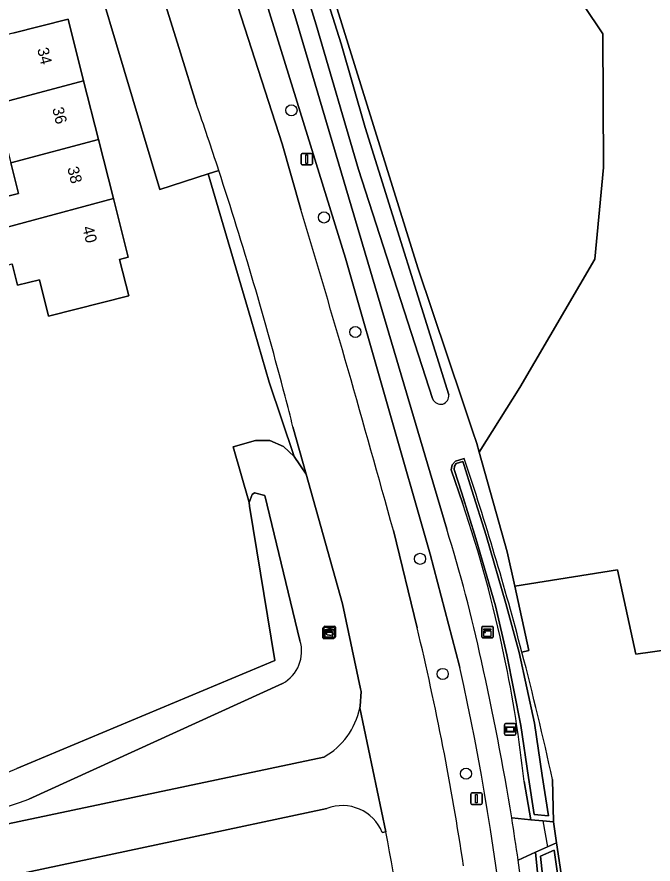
# Model space of a CAD drawing. Extents: x 162510 to 163918, y 388494 to 389774.
# Drawn here: x 162618.4 to 162674.3, y 389627.2 to 389701.6 of the extents above; entities that cross this region are included whole.
import ezdxf

# ---------------------------------------------------------------- set-up
doc = ezdxf.new("R2010")
doc.units = 0
for name, color, linetype in [('IMGEO_Berm_groen', 7, 'Continuous'), ('IMGEO_Boom', 7, 'Continuous'), ('IMGEO_Duiker', 7, 'Continuous'), ('IMGEO_Erf', 7, 'Continuous'), ('IMGEO_Fietspad_gesloten', 7, 'Continuous'), ('IMGEO_Grasland_agrarisch', 7, 'Continuous'), ('IMGEO_Groenvoorziening', 7, 'Continuous'), ('IMGEO_Kast', 7, 'Continuous'), ('IMGEO_Lichtmast', 7, 'Continuous'), ('IMGEO_Oever', 7, 'Continuous'), ('IMGEO_Pand', 7, 'Continuous'), ('IMGEO_Pand_nummerreeks', 7, 'Continuous'), ('IMGEO_Rijbaan_lokaal_gesloten', 7, 'Continuous'), ('IMGEO_Rijbaan_lokaal_halfverhard', 7, 'Continuous'), ('IMGEO_Rijbaan_lokaal_open', 7, 'Continuous'), ('IMGEO_Rioolput', 7, 'Continuous'), ('IMGEO_Verklikker', 7, 'Continuous'), ('IMGEO_Voetpad_halfverhard', 7, 'Continuous'), ('IMGEO_Waterloop', 7, 'Continuous')]:
    doc.layers.add(name, color=color, linetype=linetype)

msp = doc.modelspace()

# ---------------------------------------------------------------- linework, layer by layer
at = {"layer": 'IMGEO_Berm_groen'}
for points in [[(162657.306, 389644.486), (162657.276, 389644.598), (162654.694, 389654.432), (162647.267, 389680.414), (162625.711, 389750), (162623.648, 389756.662), (162621.623, 389756.628), (162621.069, 389756.619)], [(162621.069, 389756.619), (162623.811, 389747.513), (162627.663, 389734.752), (162631.516, 389722.082), (162634.181, 389714.087), (162636.629, 389706.24), (162641.701, 389690.442), (162643.356, 389684.664)], [(162651.468, 389656.503), (162653.554, 389647.978)], [(162645.63, 389632.117), (162606.04, 389623.696)], [(162650.812, 389630.07), (162650.498, 389630.008)]]:
    msp.add_lwpolyline(points, dxfattribs=at)
for centre, radius, start, end in [((161544.624, 389352.917), 1147.723, 15.337949, 16.800985), ((162411.673, 389589.955), 248.743, 8.58477, 13.48924), ((162441.799, 389596.346), 220.818, 359.26131, 12.59207), ((162647.001, 389628.609), 3.767, 21.80971, 111.34215), ((162495.406, 389600.134), 158.263, 0.58051, 10.90354)]:
    msp.add_arc(centre, radius, start, end, dxfattribs=at)
at = {"layer": 'IMGEO_Boom'}
for centre in [(162642.53, 389693.381), (162645.384, 389683.977), (162648.134, 389673.926), (162653.814, 389654.027), (162655.802, 389643.929), (162657.847, 389635.178)]:
    msp.add_circle(centre, 0.489, dxfattribs=at)
at = {"layer": 'IMGEO_Duiker'}
msp.add_lwpolyline([(162664.576, 389631.03), (162664.992, 389628.753)], dxfattribs=at)
at = {"layer": 'IMGEO_Erf'}
for points in [[(162618.447, 389635.627), (162641.074, 389645.121), (162638.861, 389658.639), (162638.809, 389658.955), (162637.413, 389663.853), (162639.383, 389664.401), (162640.622, 389664.401), (162641.833, 389663.89), (162642.776, 389663.003), (162640.565, 389669.518), (162638.969, 389675.09), (162635.223, 389687.803), (162630.982, 389686.434), (162627.859, 389696.902), (162625.249, 389705.649)], [(162618.089, 389700.135), (162622.936, 389701.361), (162624.3, 389695.971), (162625.603, 389690.821), (162626.911, 389685.654), (162628.217, 389680.492), (162627.441, 389680.296), (162628.251, 389677.097), (162621.222, 389675.319), (162620.413, 389678.518), (162618.51, 389678.037), (162618.038, 389679.908)], [(162613.217, 389684.726), (162618.587, 389686.084), (162617.91, 389688.761)], [(162683.399, 389647.166), (162672.749, 389645.659), (162671.119, 389653.063), (162662.113, 389651.634), (162663.364, 389645.997), (162662.745, 389645.853)], [(162665.428, 389634.667), (162665.504, 389630.941), (162665.782, 389629.105), (162667.72, 389616.266), (162671.531, 389596.525), (162682.772, 389600.017), (162694.884, 389604.331), (162700.737, 389606.566), (162706.577, 389609.521), (162708.451, 389610.469), (162716.702, 389614.898), (162716.891, 389614.546), (162708.636, 389610.114), (162706.758, 389609.164), (162700.899, 389606.2), (162695.022, 389603.956), (162682.898, 389599.637), (162671.607, 389596.13), (162671.64, 389595.959), (162671.78, 389595.085)]]:
    msp.add_lwpolyline(points, dxfattribs=at)
for centre, radius, start, end in [((162400.973, 389577.151), 270.637, 12.27004, 14.70554), ((162593.871, 389692.296), 61.768, 281.18586, 293.44497)]:
    msp.add_arc(centre, radius, start, end, dxfattribs=at)
at = {"layer": 'IMGEO_Fietspad_gesloten'}
for points in [[(162656.158, 389656.625), (162642.905, 389701.409), (162627.834, 389750), (162625.756, 389756.697), (162623.648, 389756.662)], [(162623.648, 389756.662), (162625.711, 389750), (162647.267, 389680.414), (162654.694, 389654.432), (162657.276, 389644.598), (162657.306, 389644.486)]]:
    msp.add_lwpolyline(points, dxfattribs=at)
for centre, radius, start, end in [((162533.694, 389618.315), 128.317, 12.03732, 17.37116), ((162444.215, 389596.393), 220.417, 9.11335, 12.75985), ((162441.799, 389596.346), 220.818, 359.26131, 12.59207), ((162449.24, 389597.126), 215.34, 8.13643, 9.13247), ((162443.365, 389596.276), 221.276, 0.5906, 8.13893)]:
    msp.add_arc(centre, radius, start, end, dxfattribs=at)
at = {"layer": 'IMGEO_Grasland_agrarisch'}
msp.add_lwpolyline([(162687.277, 389757.733), (162652.361, 389744.846), (162649.788, 389743.642), (162655.173, 389728.688), (162659.589, 389717.108), (162663.344, 389709.783), (162669.846, 389700.093), (162669.917, 389688.356), (162669.136, 389680.314), (162662.579, 389669.049), (162659.003, 389663.387), (162661.443, 389654.652), (162662.113, 389651.634), (162671.119, 389653.063), (162672.749, 389645.659), (162683.399, 389647.166)], dxfattribs=at)
at = {"layer": 'IMGEO_Groenvoorziening'}
for points in [[(162654.908, 389668.091), (162648.424, 389688.196), (162644.71, 389700.887), (162633.95, 389735.77), (162629.441, 389750), (162627.311, 389756.724), (162625.756, 389756.697), (162627.834, 389750), (162642.905, 389701.409), (162656.158, 389656.625)], [(162629.565, 389756.763), (162628.661, 389756.746), (162630.798, 389750), (162646.883, 389699.203), (162649.01, 389691.856), (162656.336, 389668.425)], [(162662.745, 389645.853), (162663.364, 389645.997), (162662.113, 389651.634), (162661.443, 389654.652), (162659.003, 389663.387), (162658.792, 389664.143), (162658.415, 389665.263), (162657.534, 389667.881), (162653.602, 389679.561), (162629.565, 389756.763)], [(162648.52, 389640.952), (162648.546, 389641.092), (162648.639, 389642.388), (162648.587, 389642.631), (162646.993, 389650.091), (162643.825, 389661.448), (162642.776, 389663.003), (162641.833, 389663.89), (162640.622, 389664.401), (162639.383, 389664.401), (162637.413, 389663.853), (162638.809, 389658.955), (162639.082, 389659.667), (162639.277, 389659.825), (162640.198, 389659.584), (162643.278, 389646.86)], [(162657.557, 389658.857), (162656.55, 389661.826), (162656.621, 389662.265), (162656.908, 389662.604), (162657.688, 389662.823)], [(162641.751, 389643.1), (162619.481, 389632.945)], [(162606.309, 389629.62), (162606.57, 389628.425), (162645.367, 389636.64)], [(162661.85, 389631.304), (162663.534, 389631.13), (162662.936, 389634.499)], [(162664.781, 389619.716), (162663.942, 389628.285), (162662.412, 389627.603)]]:
    msp.add_lwpolyline(points, dxfattribs=at)
msp.add_lwpolyline([(162629.565, 389756.763), (162653.602, 389679.561), (162657.534, 389667.881), (162658.415, 389665.263), (162658.792, 389664.143), (162659.003, 389663.387), (162662.579, 389669.049), (162669.136, 389680.314), (162669.917, 389688.356), (162669.846, 389700.093), (162663.344, 389709.783), (162659.589, 389717.108), (162655.173, 389728.688), (162649.788, 389743.642), (162647.635, 389742.802), (162643.424, 389750), (162639.379, 389756.914), (162639.372, 389756.927), (162636.47, 389756.878), (162631.645, 389756.797)], close=True, dxfattribs=at)
for centre, radius, start, end in [((162655.556, 389668.344), 0.784, 289.18667, 5.91611), ((162655.643, 389668.371), 0.786, 200.89435, 282.58714), ((162402.456, 389577.526), 269.107, 14.70848, 18.47926), ((162549.33, 389622.204), 114.265, 11.76157, 18.70948), ((162533.694, 389618.315), 128.317, 12.03732, 17.37116), ((162640.223, 389645.911), 3.199, 298.53368, 17.26051), ((162444.215, 389596.393), 220.417, 9.11335, 12.75985), ((162549.36, 389622.165), 114.244, 6.19805, 11.78412), ((162642.302, 389642.19), 6.34, 298.91007, 348.74025), ((162597.624, 389691.778), 62.762, 277.95404, 290.38031), ((162443.365, 389596.276), 221.276, 0.5906, 8.13893)]:
    msp.add_arc(centre, radius, start, end, dxfattribs=at)
at = {"layer": 'IMGEO_Kast'}
for p, q in [((162659.299, 389648.1), (162660.14, 389648.1)), ((162660.14, 389648.1), (162659.299, 389648.1)), ((162645.296, 389647.107), (162645.296, 389647.948)), ((162645.296, 389647.948), (162645.296, 389647.107)), ((162645.371, 389648.032), (162646.212, 389648.032)), ((162646.212, 389648.032), (162645.371, 389648.032)), ((162646.296, 389647.957), (162646.296, 389647.116)), ((162646.296, 389647.116), (162646.296, 389647.957)), ((162659.224, 389647.175), (162659.224, 389648.016)), ((162659.224, 389648.016), (162659.224, 389647.175)), ((162660.224, 389648.025), (162660.224, 389647.184)), ((162660.224, 389647.184), (162660.224, 389648.025)), ((162646.221, 389647.032), (162645.38, 389647.032)), ((162645.38, 389647.032), (162646.221, 389647.032)), ((162660.149, 389647.1), (162659.308, 389647.1)), ((162659.308, 389647.1), (162660.149, 389647.1))]:
    msp.add_line(p, q, dxfattribs=at)
for points in [[(162645.491, 389647.822), (162646.091, 389647.822), (162646.091, 389647.737), (162645.491, 389647.737), (162645.491, 389647.822)], [(162645.491, 389647.647), (162646.091, 389647.647), (162646.091, 389647.158), (162645.491, 389647.158), (162645.491, 389647.647)], [(162659.419, 389647.89), (162660.019, 389647.89), (162660.019, 389647.805), (162659.419, 389647.805), (162659.419, 389647.89)], [(162659.419, 389647.715), (162660.019, 389647.715), (162660.019, 389647.226), (162659.419, 389647.226), (162659.419, 389647.715)]]:
    msp.add_lwpolyline(points, dxfattribs=at)
for centre in [(162645.575, 389647.496), (162659.503, 389647.564)]:
    msp.add_circle(centre, 0.0377, dxfattribs=at)
for centre, start, end in [((162659.302, 389648.022), 92.4484, 184.28452), ((162659.302, 389648.022), 92.4484, 184.28452), ((162660.146, 389648.022), 2.4484, 94.28452), ((162660.146, 389648.022), 2.4484, 94.28452), ((162645.374, 389647.954), 92.4484, 184.28452), ((162645.374, 389647.954), 92.4484, 184.28452), ((162646.218, 389647.954), 2.4484, 94.28452), ((162646.218, 389647.954), 2.4484, 94.28452), ((162645.374, 389647.11), 182.4484, 274.28452), ((162645.374, 389647.11), 182.4484, 274.28452), ((162646.218, 389647.11), 272.4484, 4.28452), ((162646.218, 389647.11), 272.4484, 4.28452), ((162659.302, 389647.178), 182.4484, 274.28452), ((162659.302, 389647.178), 182.4484, 274.28452), ((162660.146, 389647.178), 272.4484, 4.28452), ((162660.146, 389647.178), 272.4484, 4.28452)]:
    msp.add_arc(centre, 0.0779, start, end, dxfattribs=at)
at = {"layer": 'IMGEO_Lichtmast'}
for p, q in [((162643.371, 389688.691), (162643.371, 389689.491)), ((162643.371, 389689.491), (162643.371, 389688.691)), ((162643.471, 389689.591), (162644.261, 389689.591)), ((162644.261, 389689.591), (162643.471, 389689.591)), ((162644.361, 389689.491), (162644.361, 389688.691)), ((162644.361, 389688.691), (162644.361, 389689.491)), ((162644.261, 389688.591), (162643.471, 389688.591)), ((162643.471, 389688.591), (162644.261, 389688.591)), ((162658.266, 389632.587), (162658.266, 389633.387)), ((162658.266, 389633.387), (162658.266, 389632.587)), ((162658.366, 389633.487), (162659.156, 389633.487)), ((162659.156, 389633.487), (162658.366, 389633.487)), ((162659.256, 389633.387), (162659.256, 389632.587)), ((162659.256, 389632.587), (162659.256, 389633.387)), ((162659.156, 389632.487), (162658.366, 389632.487)), ((162658.366, 389632.487), (162659.156, 389632.487))]:
    msp.add_line(p, q, dxfattribs=at)
for points in [[(162643.791, 389689.466), (162643.941, 389689.466), (162643.941, 389688.716), (162643.791, 389688.716), (162643.791, 389689.466)], [(162658.686, 389633.362), (162658.836, 389633.362), (162658.836, 389632.612), (162658.686, 389632.612), (162658.686, 389633.362)]]:
    msp.add_lwpolyline(points, dxfattribs=at)
for centre, start, end in [((162643.471, 389689.491), 90, 180), ((162643.471, 389689.491), 90, 180), ((162644.261, 389689.491), 0, 90), ((162644.261, 389689.491), 360, 90), ((162643.471, 389688.691), 180, 270), ((162643.471, 389688.691), 180, 270), ((162644.261, 389688.691), 270, 0), ((162644.261, 389688.691), 270, 0), ((162658.366, 389633.387), 90, 180), ((162658.366, 389633.387), 90, 180), ((162659.156, 389633.387), 0, 90), ((162659.156, 389633.387), 360, 90), ((162658.366, 389632.587), 180, 270), ((162658.366, 389632.587), 180, 270), ((162659.156, 389632.587), 270, 0), ((162659.156, 389632.587), 270, 0)]:
    msp.add_arc(centre, 0.1, start, end, dxfattribs=at)
at = {"layer": 'IMGEO_Oever'}
for points in [[(162657.688, 389662.823), (162656.908, 389662.604), (162656.621, 389662.265), (162656.55, 389661.826), (162657.557, 389658.857)], [(162662.936, 389634.499), (162663.534, 389631.13), (162664.576, 389631.03), (162665.504, 389630.941), (162665.428, 389634.667)]]:
    msp.add_lwpolyline(points, dxfattribs=at)
for points in [[(162665.077, 389631.473), (162663.826, 389631.604), (162663.317, 389634.841), (162662.644, 389639.412), (162661.418, 389645.593), (162660.421, 389649.903), (162658.716, 389655.825), (162657.478, 389659.779), (162656.79, 389661.874), (162656.82, 389662.147), (162656.983, 389662.391), (162657.578, 389662.566), (162657.69, 389662.206), (162658.359, 389660.059), (162659.598, 389656.087), (162661.342, 389650.121), (162662.508, 389645.819), (162663.843, 389639.619), (162664.52, 389635.025)], [(162665.782, 389629.105), (162664.992, 389628.753), (162663.942, 389628.285), (162664.781, 389619.716), (162669.021, 389596.399), (162670.086, 389595.68), (162671.64, 389595.959), (162671.607, 389596.13), (162671.531, 389596.525), (162667.72, 389616.266)], [(162665.576, 389628.466), (162666.774, 389620.114), (162667.664, 389614.753), (162668.816, 389608.963), (162671.265, 389596.221), (162670.102, 389596.028), (162669.408, 389596.502), (162667.305, 389608.699), (162666.28, 389614.493), (162665.235, 389619.894), (162664.385, 389627.945)]]:
    msp.add_lwpolyline(points, close=True, dxfattribs=at)
for centre, radius, start, end in [((162402.456, 389577.526), 269.107, 14.70848, 18.47926), ((162549.33, 389622.204), 114.265, 11.76157, 18.70948), ((162400.973, 389577.151), 270.637, 12.27004, 14.70554), ((162549.36, 389622.165), 114.244, 6.19805, 11.78412)]:
    msp.add_arc(centre, radius, start, end, dxfattribs=at)
at = {"layer": 'IMGEO_Pand'}
for points in [[(162622.936, 389701.361), (162618.089, 389700.135), (162615.181, 389699.399), (162615.887, 389696.671), (162610.605, 389695.335), (162611.188, 389693.03), (162611.317, 389692.522), (162624.3, 389695.971)], [(162617.91, 389688.761), (162625.603, 389690.821), (162624.3, 389695.971), (162611.317, 389692.522), (162611.997, 389689.835), (162617.299, 389691.177)], [(162612.029, 389681.374), (162613.873, 389682.136), (162626.911, 389685.654), (162625.603, 389690.821), (162617.91, 389688.761), (162618.587, 389686.084), (162613.217, 389684.726), (162611.304, 389684.242)], [(162626.911, 389685.654), (162613.873, 389682.136), (162612.029, 389681.374), (162612.267, 389680.432), (162611.785, 389680.309), (162611.202, 389680.161), (162610.332, 389679.939), (162610.133, 389679.889), (162611.263, 389675.42), (162615.49, 389676.489), (162614.83, 389679.097), (162617.516, 389679.776), (162618.038, 389679.908), (162618.51, 389678.037), (162620.413, 389678.518), (162621.222, 389675.319), (162628.251, 389677.097), (162627.441, 389680.296), (162628.217, 389680.492)]]:
    msp.add_lwpolyline(points, close=True, dxfattribs=at)
at = {"layer": 'IMGEO_Rijbaan_lokaal_gesloten'}
for points in [[(162643.356, 389684.664), (162641.701, 389690.442), (162636.629, 389706.24), (162634.181, 389714.087), (162631.516, 389722.082), (162627.663, 389734.752), (162623.811, 389747.513), (162621.069, 389756.619), (162614.746, 389756.512)], [(162614.746, 389756.512), (162616.763, 389750), (162624.646, 389724.639), (162625.196, 389722.87), (162627.614, 389715.092), (162627.673, 389714.901), (162630.082, 389707.151), (162632.791, 389698.435), (162634.173, 389693.988)], [(162642.662, 389665.619), (162643.825, 389661.448), (162646.993, 389650.091), (162648.587, 389642.631), (162648.639, 389642.388), (162648.546, 389641.092), (162648.52, 389640.952), (162650.812, 389630.07)], [(162653.554, 389647.978), (162651.468, 389656.503)]]:
    msp.add_lwpolyline(points, dxfattribs=at)
for centre, radius, start, end in [((162310.638, 389581.786), 342.438, 18.08773, 19.12653), ((162307.447, 389580.769), 345.788, 14.66153, 18.08373), ((161544.624, 389352.917), 1147.723, 15.337949, 16.800985), ((162297.232, 389578.23), 356.312, 14.19723, 14.64087), ((162411.673, 389589.955), 248.743, 8.58477, 13.48924), ((162495.406, 389600.134), 158.263, 0.58051, 10.90354)]:
    msp.add_arc(centre, radius, start, end, dxfattribs=at)
at = {"layer": 'IMGEO_Rijbaan_lokaal_halfverhard'}
msp.add_lwpolyline([(162636.154, 389688.104), (162635.223, 389687.803), (162638.969, 389675.09), (162640.565, 389669.518), (162642.776, 389663.003), (162643.825, 389661.448), (162642.662, 389665.619)], dxfattribs=at)
for centre, radius, start, end in [((162307.447, 389580.769), 345.788, 14.66153, 18.08373), ((162297.232, 389578.23), 356.312, 14.19723, 14.64087)]:
    msp.add_arc(centre, radius, start, end, dxfattribs=at)
at = {"layer": 'IMGEO_Rijbaan_lokaal_open'}
for points in [[(162632.791, 389698.435), (162630.082, 389707.151), (162628.847, 389706.767), (162625.249, 389705.649), (162627.859, 389696.902), (162630.982, 389686.434), (162635.223, 389687.803), (162636.154, 389688.104)], [(162634.173, 389693.988), (162632.791, 389698.435)], [(162650.498, 389630.008), (162650.812, 389630.07), (162648.52, 389640.952)], [(162645.367, 389636.64), (162606.57, 389628.425), (162605.4, 389628.177)], [(162606.04, 389623.696), (162645.63, 389632.117)]]:
    msp.add_lwpolyline(points, dxfattribs=at)
for centre, radius, start, end in [((162310.638, 389581.786), 342.438, 18.08773, 19.12653), ((162642.302, 389642.19), 6.34, 298.91007, 348.74025), ((162647.001, 389628.609), 3.767, 21.80971, 111.34215)]:
    msp.add_arc(centre, radius, start, end, dxfattribs=at)
at = {"layer": 'IMGEO_Rioolput'}
for p, q in [((162645.461, 389648.115), (162646.313, 389648.115)), ((162645.386, 389647.189), (162645.386, 389648.041)), ((162645.645, 389647.609), (162645.645, 389647.621)), ((162646.083, 389647.572), (162645.685, 389647.572)), ((162645.688, 389647.658), (162646.086, 389647.658)), ((162645.897, 389647.335), (162645.872, 389647.335)), ((162645.874, 389647.895), (162645.899, 389647.895)), ((162646.129, 389647.621), (162646.129, 389647.609)), ((162646.387, 389648.041), (162646.387, 389647.189)), ((162646.313, 389647.115), (162645.461, 389647.115))]:
    msp.add_line(p, q, dxfattribs=at)
for points in [[(162645.461, 389648.115), (162646.313, 389648.115)], [(162645.386, 389647.189), (162645.386, 389648.041)], [(162646.387, 389648.041), (162646.387, 389647.189)], [(162646.313, 389647.115), (162645.461, 389647.115)]]:
    msp.add_lwpolyline(points, dxfattribs=at)
for centre, radius, start, end in [((162645.463, 389648.039), 0.0765, 91.55205, 178.44795), ((162645.463, 389648.039), 0.0765, 91.55205, 178.44795), ((162646.311, 389648.039), 0.0765, 1.55205, 88.44795), ((162646.311, 389648.039), 0.0765, 1.55205, 88.44795), ((162645.685, 389647.618), 0.0403, 85.87752, 175.75265), ((162645.682, 389647.608), 0.0366, 178.93798, 274.71019), ((162646.086, 389647.615), 0.043, 264.86636, 352.45326), ((162646.09, 389647.62), 0.0386, 1.73085, 96.63898), ((162645.463, 389647.191), 0.0765, 181.55205, 268.44795), ((162645.463, 389647.191), 0.0765, 181.55205, 268.44795), ((162646.311, 389647.191), 0.0765, 271.55205, 358.44795), ((162646.311, 389647.191), 0.0765, 271.55205, 358.44795)]:
    msp.add_arc(centre, radius, start, end, dxfattribs=at)
for centre, major_axis, ratio, start_param, end_param in [((162645.873, 389647.615), (-0.387, 0.002), 0.722429, 4.712389, 7.853982), ((162645.898, 389647.615), (-0.39, 0.002), 0.717154, 1.570796, 4.712389)]:
    msp.add_ellipse(centre, major_axis=major_axis, ratio=ratio, start_param=start_param, end_param=end_param, dxfattribs=at)
at = {"layer": 'IMGEO_Verklikker'}
for p, q in [((162661.218, 389638.666), (162661.218, 389639.466)), ((162661.218, 389639.466), (162661.218, 389638.666)), ((162661.318, 389639.566), (162662.108, 389639.566)), ((162662.108, 389639.566), (162661.318, 389639.566)), ((162662.208, 389639.466), (162662.208, 389638.666)), ((162662.208, 389638.666), (162662.208, 389639.466)), ((162662.108, 389638.566), (162661.318, 389638.566)), ((162661.318, 389638.566), (162662.108, 389638.566))]:
    msp.add_line(p, q, dxfattribs=at)
for points in [[(162661.319, 389639.298), (162662.107, 389639.298), (162662.107, 389638.834), (162661.319, 389638.834), (162661.319, 389639.298)], [(162661.384, 389639.233), (162661.384, 389638.899), (162662.042, 389638.899), (162662.042, 389639.233), (162661.384, 389639.233)]]:
    msp.add_lwpolyline(points, dxfattribs=at)
for centre, start, end in [((162661.318, 389639.466), 90, 180), ((162661.318, 389639.466), 90, 180), ((162662.108, 389639.466), 0, 90), ((162662.108, 389639.466), 360, 90), ((162661.318, 389638.666), 180, 270), ((162661.318, 389638.666), 180, 270), ((162662.108, 389638.666), 270, 0), ((162662.108, 389638.666), 270, 0)]:
    msp.add_arc(centre, 0.1, start, end, dxfattribs=at)
at = {"layer": 'IMGEO_Voetpad_halfverhard'}
for points in [[(162665.504, 389630.941), (162664.576, 389631.03), (162663.534, 389631.13), (162661.85, 389631.304)], [(162662.412, 389627.603), (162663.942, 389628.285), (162664.992, 389628.753), (162665.782, 389629.105), (162665.504, 389630.941)]]:
    msp.add_lwpolyline(points, dxfattribs=at)
msp.add_arc((162449.24, 389597.126), 215.34, 8.13643, 9.13247, dxfattribs=at)
at = {"layer": 'IMGEO_Waterloop'}
for points in [[(162656.336, 389668.425), (162649.01, 389691.856), (162646.883, 389699.203), (162630.798, 389750), (162628.661, 389756.746), (162627.311, 389756.724)], [(162627.311, 389756.724), (162629.441, 389750), (162633.95, 389735.77), (162644.71, 389700.887), (162648.424, 389688.196), (162654.908, 389668.091)], [(162643.278, 389646.86), (162640.198, 389659.584), (162639.277, 389659.825), (162639.082, 389659.667), (162638.809, 389658.955), (162638.861, 389658.639), (162641.074, 389645.121), (162618.447, 389635.627)], [(162619.481, 389632.945), (162641.751, 389643.1)]]:
    msp.add_lwpolyline(points, dxfattribs=at)
for points in [[(162657.69, 389662.206), (162657.578, 389662.566), (162656.983, 389662.391), (162656.82, 389662.147), (162656.79, 389661.874), (162657.478, 389659.779), (162658.716, 389655.825), (162660.421, 389649.903), (162661.418, 389645.593), (162662.644, 389639.412), (162663.317, 389634.841), (162663.826, 389631.604), (162665.077, 389631.473), (162664.52, 389635.025), (162663.843, 389639.619), (162662.508, 389645.819), (162661.342, 389650.121), (162659.598, 389656.087), (162658.359, 389660.059)], [(162665.576, 389628.466), (162664.385, 389627.945), (162665.235, 389619.894), (162666.28, 389614.493), (162667.305, 389608.699), (162669.408, 389596.502), (162670.102, 389596.028), (162671.265, 389596.221), (162668.816, 389608.963), (162667.664, 389614.753), (162666.774, 389620.114)]]:
    msp.add_lwpolyline(points, close=True, dxfattribs=at)
for centre, radius, start, end in [((162655.556, 389668.344), 0.784, 289.18667, 5.91611), ((162655.643, 389668.371), 0.786, 200.89435, 282.58714), ((162640.223, 389645.911), 3.199, 298.53368, 17.26051), ((162593.871, 389692.296), 61.768, 281.18586, 293.44497), ((162597.624, 389691.778), 62.762, 277.95404, 290.38031)]:
    msp.add_arc(centre, radius, start, end, dxfattribs=at)

# ---------------------------------------------------------------- texts
at = {"layer": 'IMGEO_Pand_nummerreeks'}
for s, rotation, p in [('34', 284.20341, (162620.214, 389698.748)), ('36', 284.20086, (162621.534, 389693.532)), ('38', 284.20086, (162622.855, 389688.311)), ('40', 284.20341, (162624.175, 389683.093))]:
    msp.add_text(s, height=1, rotation=rotation, dxfattribs=at).set_placement(p)

doc.saveas('drawing.dxf')
